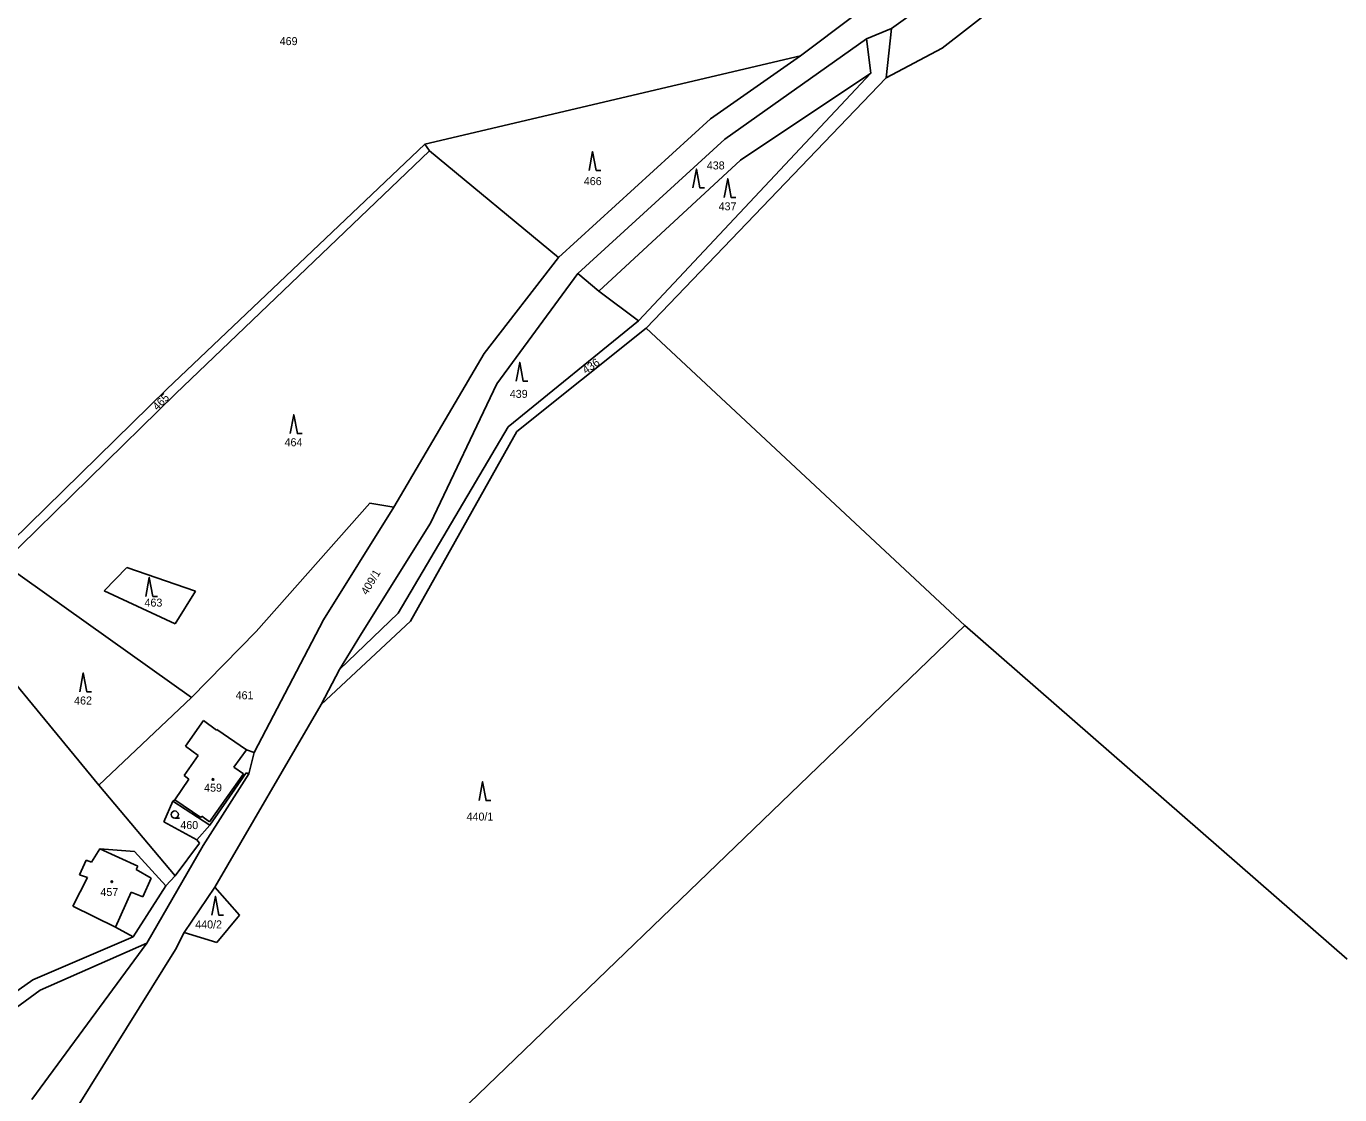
# Model space of a CAD drawing. Extents: x -670359 to -668019, y -978807 to -976674.
# Drawn here: x -668879.1 to -668600.1, y -977190.9 to -976964 of the extents above; entities that cross this region are included whole.
import ezdxf

# ---------------------------------------------------------------- set-up
doc = ezdxf.new("R2010")
doc.units = 0
for name, color, linetype in [('Hranice parcel', 7, 'Continuous'), ('Parcelní čísla', 7, 'Continuous'), ('Vnitřní kresba', 7, 'Continuous'), ('Značky budov', 7, 'Continuous'), ('Značky kultur', 7, 'Continuous')]:
    doc.layers.add(name, color=color, linetype=linetype)

msp = doc.modelspace()

# ---------------------------------------------------------------- linework, layer by layer
at = {"layer": 'Hranice parcel'}
for p, q in [((-668845.26, -977116.88), (-668841.44, -977111.49)), ((-668841.44, -977111.49), (-668838.7, -977113.52)), ((-668838.7, -977113.52), (-668838.62, -977113.38)), ((-668838.62, -977113.38), (-668832.31, -977117.72)), ((-668842.53, -977118.88), (-668845.26, -977116.88)), ((-668832.31, -977117.72), (-668830.7, -977118.27)), ((-668845.51, -977123.16), (-668842.53, -977118.88)), ((-668844.52, -977123.88), (-668845.51, -977123.16)), ((-668832.36, -977122.59), (-668840.12, -977133.69)), ((-668832.36, -977122.59), (-668831.83, -977122.75)), ((-668847.54, -977128.33), (-668844.52, -977123.88)), ((-668847.94, -977128.62), (-668847.54, -977128.33)), ((-668840.12, -977133.69), (-668847.94, -977128.62)), ((-668842.85, -977136.8), (-668840.12, -977133.69))]:
    msp.add_line(p, q, dxfattribs=at)
for points in [[(-668695.31, -976964.49), (-668670, -976946.29)], [(-668703.22, -976961.78), (-668714.63, -976970.3)], [(-668684.58, -976968.68), (-668673.18, -976959.83)], [(-668695.31, -976964.49), (-668700.61, -976966.72)], [(-668696.47, -976975), (-668695.31, -976964.49)], [(-668700.61, -976966.72), (-668730.68, -976987.99)], [(-668699.68, -976974.03), (-668700.61, -976966.72)], [(-668794.4, -976989.09), (-668714.63, -976970.3)], [(-668714.63, -976970.3), (-668733.72, -976983.72)], [(-668696.47, -976975), (-668684.58, -976968.68)], [(-668749.05, -977026.61), (-668699.68, -976974.03)], [(-668747.41, -977028.17), (-668696.47, -976975)], [(-668727.38, -976992.48), (-668699.68, -976974.03)], [(-668733.72, -976983.72), (-668766, -977013.17)], [(-668794.4, -976989.09), (-668849.2, -977041.1)], [(-668793.42, -976990.46), (-668794.4, -976989.09)], [(-668730.68, -976987.99), (-668761.9, -977016.56)], [(-668793.42, -976990.46), (-668847.36, -977042.09)], [(-668766, -977013.17), (-668793.42, -976990.46)], [(-668757.46, -977020.32), (-668727.38, -976992.48)], [(-668766, -977013.17), (-668781.85, -977033.56)], [(-668761.9, -977016.56), (-668779.14, -977039.94)], [(-668761.9, -977016.56), (-668757.46, -977020.32)], [(-668757.46, -977020.32), (-668749.05, -977026.61)], [(-668776.71, -977049.07), (-668749.05, -977026.61)], [(-668774.87, -977050.06), (-668747.41, -977028.17)], [(-668679.76, -977091.25), (-668747.41, -977028.17)], [(-668781.85, -977033.56), (-668800.98, -977066.19)], [(-668779.14, -977039.94), (-668793.22, -977069.57)], [(-668847.36, -977042.09), (-668884.04, -977078.04)], [(-668849.2, -977041.1), (-668882.19, -977073.48)], [(-668800.09, -977088.67), (-668776.71, -977049.07)], [(-668797.45, -977090.36), (-668774.87, -977050.06)], [(-668806.1, -977065.29), (-668830.21, -977092.59)], [(-668815.95, -977090.07), (-668800.98, -977066.19)], [(-668800.98, -977066.19), (-668806.1, -977065.29)], [(-668793.22, -977069.57), (-668807.87, -977092.97)], [(-668843.95, -977106.55), (-668884.04, -977078.04)], [(-668862.53, -977083.94), (-668857.71, -977078.99)], [(-668857.71, -977078.99), (-668843.15, -977083.99)], [(-668847.42, -977090.94), (-668862.53, -977083.94)], [(-668843.15, -977083.99), (-668847.42, -977090.94)], [(-668863.63, -977125.22), (-668895.52, -977086.57)], [(-668830.7, -977118.27), (-668815.95, -977090.07)], [(-668812.54, -977100.64), (-668800.09, -977088.67)], [(-668830.21, -977092.59), (-668843.95, -977106.55)], [(-668679.76, -977091.25), (-668818.16, -977224.64)], [(-668816.41, -977108.07), (-668797.45, -977090.36)], [(-668807.87, -977092.97), (-668812.54, -977100.64)], [(-668598.5, -977162.16), (-668679.76, -977091.25)], [(-668812.54, -977100.64), (-668816.41, -977108.07)], [(-668843.95, -977106.55), (-668863.63, -977125.22)], [(-668816.41, -977108.07), (-668839.05, -977146.84)], [(-668831.83, -977122.75), (-668830.7, -977118.27)], [(-668831.83, -977122.75), (-668841.49, -977138)], [(-668863.63, -977125.22), (-668847.44, -977144.47)], [(-668849.88, -977132.94), (-668847.94, -977128.62)], [(-668842.85, -977136.8), (-668849.88, -977132.94)], [(-668847.44, -977144.47), (-668842.29, -977137.52)], [(-668842.29, -977137.52), (-668842.85, -977136.8)], [(-668863.43, -977138.74), (-668865.2, -977141.54)], [(-668856.07, -977139.24), (-668863.43, -977138.74)], [(-668849.45, -977146.54), (-668856.07, -977139.24)], [(-668841.49, -977138), (-668853.49, -977158.77)], [(-668866.32, -977141.14), (-668867.77, -977144.25)], [(-668865.2, -977141.54), (-668866.32, -977141.14)], [(-668866.09, -977144.82), (-668869.16, -977150.89)], [(-668867.77, -977144.25), (-668866.09, -977144.82)], [(-668847.44, -977144.47), (-668849.45, -977146.54)], [(-668849.45, -977146.54), (-668856.37, -977157.4)], [(-668839.05, -977146.84), (-668845.55, -977156.5)], [(-668839.05, -977146.84), (-668833.76, -977152.81)], [(-668869.16, -977150.89), (-668860.12, -977155.31)], [(-668833.76, -977152.81), (-668838.59, -977158.61)], [(-668860.12, -977155.31), (-668856.37, -977157.4)], [(-668845.55, -977156.5), (-668847.41, -977160.07)], [(-668838.59, -977158.61), (-668845.55, -977156.5)], [(-668853.49, -977158.77), (-668877.86, -977191.91)], [(-668856.37, -977157.4), (-668877.7, -977166.55)], [(-668853.49, -977158.77), (-668876.1, -977168.71)], [(-668847.41, -977160.07), (-668880.9, -977213.98)], [(-668877.7, -977166.55), (-668911.08, -977190.06)], [(-668876.1, -977168.71), (-668907.97, -977191.98)]]:
    msp.add_lwpolyline(points, dxfattribs=at)
at = {"layer": 'Vnitřní kresba'}
for p, q in [((-668832.31, -977117.72), (-668835, -977121.37)), ((-668832.95, -977122.77), (-668840.14, -977132.95)), ((-668835, -977121.37), (-668832.95, -977122.77)), ((-668841.97, -977132.07), (-668847.54, -977128.33)), ((-668841.76, -977131.78), (-668841.97, -977132.07)), ((-668840.14, -977132.95), (-668841.76, -977131.78))]:
    msp.add_line(p, q, dxfattribs=at)
for points in [[(-668863.43, -977138.74), (-668855.36, -977142.37)], [(-668855.36, -977142.37), (-668855.76, -977143.08)], [(-668855.76, -977143.08), (-668852.56, -977144.93)], [(-668852.56, -977144.93), (-668854.34, -977148.93)], [(-668856.82, -977147.88), (-668860.12, -977155.31)], [(-668854.34, -977148.93), (-668856.82, -977147.88)]]:
    msp.add_lwpolyline(points, dxfattribs=at)
at = {"layer": 'Značky budov'}
for centre in [(-668839.41, -977123.97), (-668860.9, -977145.69)]:
    msp.add_circle(centre, 0.175, dxfattribs=at)
at = {"layer": 'Značky kultur'}
msp.add_line((-668847.52, -977132.17), (-668846.52, -977132.17), dxfattribs=at)
for points in [[(-668759.53, -976994.66), (-668758.78, -976990.66), (-668758.03, -976994.66), (-668757.03, -976994.66)], [(-668737.5, -976998.37), (-668736.75, -976994.37), (-668736, -976998.37), (-668735, -976998.37)], [(-668730.85, -977000.42), (-668730.1, -976996.42), (-668729.35, -977000.42), (-668728.35, -977000.42)], [(-668775.03, -977039.42), (-668774.28, -977035.42), (-668773.53, -977039.42), (-668772.53, -977039.42)], [(-668823, -977050.52), (-668822.25, -977046.52), (-668821.5, -977050.52), (-668820.5, -977050.52)], [(-668853.69, -977085.09), (-668852.94, -977081.09), (-668852.19, -977085.09), (-668851.19, -977085.09)], [(-668867.73, -977105.36), (-668866.98, -977101.36), (-668866.23, -977105.36), (-668865.23, -977105.36)], [(-668782.9, -977128.47), (-668782.15, -977124.47), (-668781.4, -977128.47), (-668780.4, -977128.47)], [(-668839.66, -977152.8), (-668838.91, -977148.8), (-668838.16, -977152.8), (-668837.16, -977152.8)]]:
    msp.add_lwpolyline(points, dxfattribs=at)
for centre, radius in [((-668839.41, -977123.97), 0.175), ((-668847.52, -977131.42), 0.75), ((-668860.9, -977145.69), 0.175)]:
    msp.add_circle(centre, radius, dxfattribs=at)

# ---------------------------------------------------------------- texts
at = {"layer": 'Parcelní čísla'}
for s, p in [('469', (-668825.25, -976968.04)), ('438', (-668734.54, -976994.44)), ('466', (-668760.66, -976997.77)), ('437', (-668732.03, -977003.12)), ('439', (-668776.38, -977042.95)), ('464', (-668824.21, -977053.22)), ('463', (-668853.96, -977087.27)), ('462', (-668868.91, -977108.06)), ('461', (-668834.61, -977106.95)), ('459', (-668841.3, -977126.57)), ('440/1', (-668785.56, -977132.71)), ('460', (-668846.35, -977134.51)), ('457', (-668863.32, -977148.72)), ('440/2', (-668843.19, -977155.61))]:
    msp.add_text(s, height=1.7, dxfattribs=at).set_placement(p)
for s, rotation, p in [('436', 34.5923, (-668760.23, -977037.96)), ('465', 45, (-668851.24, -977045.73)), ('409/1', 58.9433, (-668806.68, -977084.93))]:
    msp.add_text(s, height=1.7, rotation=rotation, dxfattribs=at).set_placement(p)

doc.saveas('drawing.dxf')
